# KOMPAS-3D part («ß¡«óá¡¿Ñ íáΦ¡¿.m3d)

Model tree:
1. Эскиз:1
2. Операция выдавливания:1
     Расстояние 1 = 2; Расстояние 2 = 1.1
3. Эскиз:2
4. Операция выдавливания:2
     Расстояние 1 = 1.5; Расстояние 2 = 1.1
5. Эскиз:3
6. Операция выдавливания:3
     Расстояние 1 = 4; Расстояние 2 = 1.1
7. Эскиз:4
8. Операция выдавливания:4
     Расстояние 1 = 11; Расстояние 2 = 1.1
9. Эскиз:5
10. Операция выдавливания:5
     Расстояние 1 = 20; Расстояние 2 = 1.1
11. Эскиз:6
12. Вырезать элемент выдавливания:1
     Расстояние 2 = 4; Расстояние 1 = 38.5
13. Эскиз:7
14. Вырезать элемент вращения:1
     Угол 1 = 360
15. Эскиз:8
16. Вырезать элемент выдавливания:2
     Расстояние 2 = 4; Расстояние 1 = 5
17. Массив по концентрической сетке:1  (with: Вырезать элемент выдавливания:2)  (labels: Экземпляр ( 1, 1 ); Экземпляр ( 1, 2 ); Экземпляр ( 1, 3 ); Экземпляр ( 1, 4 ))
     Шаг 1 = 10; Шаг 2 = 360; Номер 2 = 1
18. Эскиз:9
19. Операция выдавливания:6
     Расстояние 1 = 22.4; Расстояние 2 = 1.1
20. Эскиз:10
21. Вырезать элемент выдавливания:3
     Расстояние 2 = 4; Расстояние 1 = 97.223
22. Эскиз:11
23. Вырезать элемент выдавливания:4
     Расстояние 2 = 4; Расстояние 1 = 97.223
24. Эскиз:12
25. Операция выдавливания:7
     Расстояние 1 = 0.1
26. Эскиз:13
27. Вырезать элемент выдавливания:5
     Расстояние 1 = 10
28. Скругление:1  (with: Эскиз:14)
     Радиус = 1
29. Вырезать элемент выдавливания:6
     Расстояние 1 = 2
30. Операция выдавливания:8
     Расстояние 1 = 2; Расстояние 2 = 30
31. Эскиз:15
32. Вырезать элемент выдавливания:7
     Расстояние 1 = 3

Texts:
  Сплав АЛ8  ГОСТ 1583-93
  stalker61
